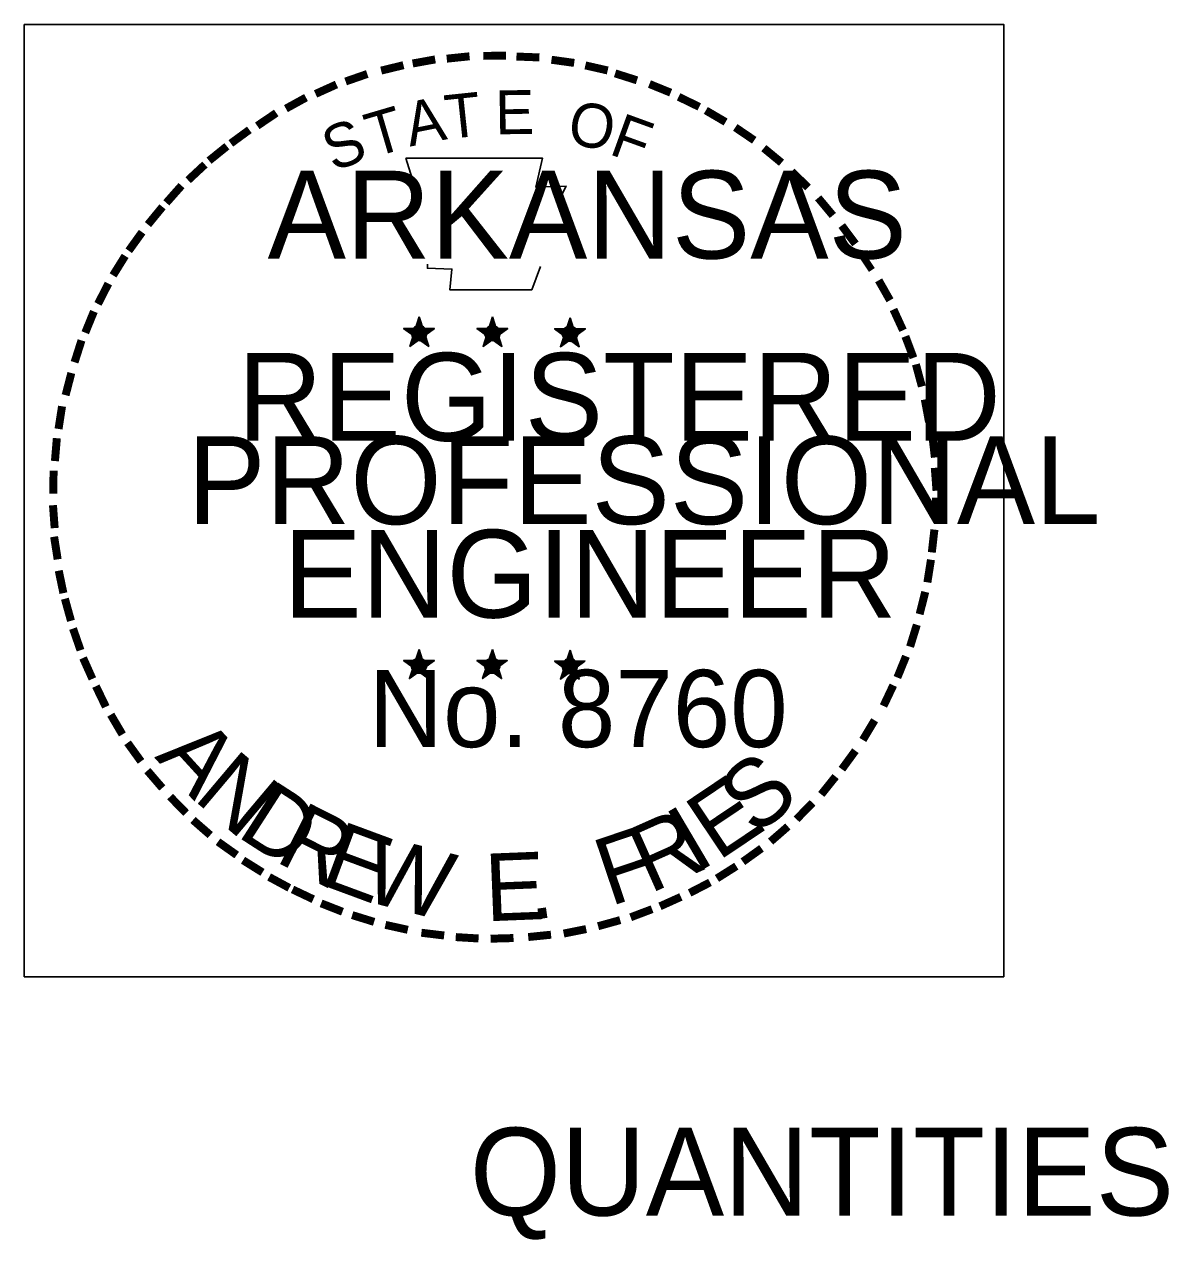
# Model space of a CAD drawing. Extents: x 1226567 to 1228151, y 151309 to 152305.
# Drawn here: x 1227967.3 to 1228130.3, y 151309.4 to 151482.4 of the extents above; entities that cross this region are included whole.
import ezdxf

# ---------------------------------------------------------------- set-up
doc = ezdxf.new("R2010")
doc.units = 0
for name, color, linetype in [('R_Border Notes', 7, 'Continuous'), ('R_Border PE', 7, 'Continuous'), ('R_Border Prem', 7, 'Continuous')]:
    doc.layers.add(name, color=color, linetype=linetype)

msp = doc.modelspace()

# ---------------------------------------------------------------- linework, layer by layer
at = {"layer": 'R_Border PE'}
for p, q in [((1228023.55, 151440.77), (1228023.24, 151439.21)), ((1228023.55, 151440.77), (1228023.3, 151439.15)), ((1228023.55, 151440.77), (1228023.49, 151439.21)), ((1228023.55, 151438.46), (1228023.55, 151440.77)), ((1228023.55, 151440.77), (1228023.99, 151439.15)), ((1228023.55, 151440.77), (1228023.86, 151439.21)), ((1228023.55, 151440.77), (1228023.74, 151439.21)), ((1228033.99, 151440.77), (1228033.68, 151439.21)), ((1228033.99, 151440.77), (1228033.74, 151439.15)), ((1228033.99, 151440.77), (1228033.86, 151439.21)), ((1228033.99, 151438.46), (1228033.99, 151440.77)), ((1228033.99, 151440.77), (1228034.43, 151439.15)), ((1228033.99, 151440.77), (1228034.3, 151439.21)), ((1228033.99, 151440.77), (1228034.11, 151439.21)), ((1228045.05, 151440.65), (1228044.68, 151439.15)), ((1228045.05, 151440.65), (1228044.8, 151439.09)), ((1228045.05, 151440.65), (1228044.93, 151439.09)), ((1228045.05, 151438.4), (1228045.05, 151440.65)), ((1228045.05, 151440.65), (1228045.49, 151439.09)), ((1228045.05, 151440.65), (1228045.36, 151439.09)), ((1228045.05, 151440.65), (1228045.18, 151439.15)), ((1228021.36, 151439.15), (1228023.55, 151438.46)), ((1228021.36, 151439.15), (1228022.99, 151439.02)), ((1228021.36, 151439.15), (1228022.99, 151438.9)), ((1228021.36, 151439.15), (1228022.93, 151438.77)), ((1228021.36, 151439.15), (1228022.93, 151438.52)), ((1228021.36, 151439.15), (1228022.86, 151438.4)), ((1228021.36, 151439.15), (1228022.86, 151438.27)), ((1228022.24, 151436.59), (1228023.55, 151438.46)), ((1228022.24, 151436.59), (1228022.93, 151438.34)), ((1228022.24, 151436.59), (1228022.99, 151438.15)), ((1228022.24, 151436.59), (1228023.11, 151438.09)), ((1228022.24, 151436.59), (1228023.55, 151437.96)), ((1228022.24, 151436.59), (1228023.3, 151437.9)), ((1228022.24, 151436.59), (1228023.61, 151437.77)), ((1228025.74, 151439.15), (1228023.55, 151438.46)), ((1228024.93, 151436.59), (1228023.55, 151438.46)), ((1228024.93, 151436.59), (1228023.55, 151437.96)), ((1228024.93, 151436.59), (1228023.55, 151437.77)), ((1228025.74, 151439.15), (1228023.8, 151439.02)), ((1228024.93, 151436.59), (1228023.8, 151437.9)), ((1228025.74, 151439.15), (1228023.93, 151438.84)), ((1228025.74, 151439.15), (1228023.93, 151438.71)), ((1228024.93, 151436.59), (1228023.99, 151438.15)), ((1228024.93, 151436.59), (1228024.05, 151438.4)), ((1228024.93, 151436.59), (1228024.18, 151438.46)), ((1228025.74, 151439.15), (1228024.36, 151438.59)), ((1228025.74, 151439.15), (1228024.49, 151438.52)), ((1228025.74, 151439.15), (1228024.55, 151438.46)), ((1228031.8, 151439.15), (1228033.99, 151438.46)), ((1228031.8, 151439.15), (1228033.43, 151439.02)), ((1228031.8, 151439.15), (1228033.43, 151438.9)), ((1228031.8, 151439.15), (1228033.36, 151438.77)), ((1228031.8, 151439.15), (1228033.3, 151438.52)), ((1228031.8, 151439.15), (1228033.3, 151438.4)), ((1228031.8, 151439.15), (1228033.3, 151438.27)), ((1228032.68, 151436.59), (1228033.99, 151438.46)), ((1228032.68, 151436.59), (1228033.36, 151438.34)), ((1228032.68, 151436.59), (1228033.43, 151438.15)), ((1228032.68, 151436.59), (1228033.55, 151438.09)), ((1228032.68, 151436.59), (1228033.99, 151437.96)), ((1228032.68, 151436.59), (1228033.74, 151437.9)), ((1228032.68, 151436.59), (1228034.05, 151437.77)), ((1228036.18, 151439.15), (1228033.99, 151438.46)), ((1228035.36, 151436.59), (1228033.99, 151438.46)), ((1228035.36, 151436.59), (1228033.99, 151437.96)), ((1228035.36, 151436.59), (1228033.99, 151437.77)), ((1228036.18, 151439.15), (1228034.24, 151439.02)), ((1228035.36, 151436.59), (1228034.24, 151437.9)), ((1228036.18, 151439.15), (1228034.36, 151438.84)), ((1228036.18, 151439.15), (1228034.36, 151438.71)), ((1228035.36, 151436.59), (1228034.43, 151438.15)), ((1228035.36, 151436.59), (1228034.49, 151438.4)), ((1228035.36, 151436.59), (1228034.61, 151438.46)), ((1228036.18, 151439.15), (1228034.8, 151438.59)), ((1228036.18, 151439.15), (1228034.93, 151438.52)), ((1228036.18, 151439.15), (1228034.99, 151438.46)), ((1228042.86, 151439.09), (1228045.05, 151438.4)), ((1228042.86, 151439.09), (1228044.49, 151438.9)), ((1228042.86, 151439.09), (1228044.43, 151438.77)), ((1228042.86, 151439.09), (1228044.43, 151438.71)), ((1228042.86, 151439.09), (1228044.36, 151438.46)), ((1228042.86, 151439.09), (1228044.36, 151438.34)), ((1228042.86, 151439.09), (1228044.36, 151438.21)), ((1228043.68, 151436.52), (1228045.05, 151438.4)), ((1228043.68, 151436.52), (1228044.43, 151438.27)), ((1228043.68, 151436.52), (1228044.49, 151438.09)), ((1228043.68, 151436.52), (1228044.61, 151438.02)), ((1228043.68, 151436.52), (1228045.05, 151437.9)), ((1228043.68, 151436.52), (1228044.8, 151437.84)), ((1228043.68, 151436.52), (1228045.11, 151437.71)), ((1228047.24, 151439.09), (1228045.05, 151438.4)), ((1228046.36, 151436.52), (1228045.05, 151438.4)), ((1228046.36, 151436.52), (1228045.05, 151437.9)), ((1228046.36, 151436.52), (1228045.05, 151437.71)), ((1228047.24, 151439.09), (1228045.3, 151438.96)), ((1228046.36, 151436.52), (1228045.3, 151437.84)), ((1228047.24, 151439.09), (1228045.43, 151438.77)), ((1228047.24, 151439.09), (1228045.43, 151438.65)), ((1228046.36, 151436.52), (1228045.49, 151438.09)), ((1228046.36, 151436.52), (1228045.55, 151438.34)), ((1228046.36, 151436.52), (1228045.68, 151438.34)), ((1228047.24, 151439.09), (1228045.86, 151438.52)), ((1228047.24, 151439.09), (1228045.93, 151438.46)), ((1228047.24, 151439.09), (1228046.05, 151438.4)), ((1228023.55, 151393.4), (1228023.18, 151391.9)), ((1228023.55, 151393.4), (1228023.3, 151391.84)), ((1228023.55, 151393.4), (1228023.43, 151391.84)), ((1228023.55, 151391.15), (1228023.55, 151393.4)), ((1228023.55, 151393.4), (1228023.99, 151391.84)), ((1228023.55, 151393.4), (1228023.86, 151391.84)), ((1228023.55, 151393.4), (1228023.68, 151391.84)), ((1228033.99, 151393.4), (1228033.61, 151391.9)), ((1228033.99, 151393.4), (1228033.74, 151391.84)), ((1228033.99, 151393.4), (1228033.86, 151391.84)), ((1228033.99, 151391.15), (1228033.99, 151393.4)), ((1228033.99, 151393.4), (1228034.36, 151391.84)), ((1228033.99, 151393.4), (1228034.3, 151391.84)), ((1228033.99, 151393.4), (1228034.11, 151391.84)), ((1228045.05, 151393.34), (1228044.68, 151391.77)), ((1228045.05, 151393.34), (1228044.8, 151391.77)), ((1228045.05, 151393.34), (1228044.93, 151391.77)), ((1228045.05, 151391.09), (1228045.05, 151393.34)), ((1228045.05, 151393.34), (1228045.43, 151391.77)), ((1228045.05, 151393.34), (1228045.36, 151391.77)), ((1228045.05, 151393.34), (1228045.18, 151391.77)), ((1228021.36, 151391.84), (1228023.55, 151391.15)), ((1228021.36, 151391.84), (1228022.99, 151391.65)), ((1228021.36, 151391.84), (1228022.93, 151391.52)), ((1228021.36, 151391.84), (1228022.93, 151391.46)), ((1228021.36, 151391.84), (1228022.86, 151391.21)), ((1228021.36, 151391.84), (1228022.86, 151391.09)), ((1228021.36, 151391.84), (1228022.86, 151390.96)), ((1228022.18, 151389.27), (1228023.55, 151391.15)), ((1228022.18, 151389.27), (1228022.93, 151391.02)), ((1228025.74, 151391.84), (1228023.55, 151391.15)), ((1228024.86, 151389.27), (1228023.55, 151391.15)), ((1228025.74, 151391.84), (1228023.8, 151391.71)), ((1228025.74, 151391.84), (1228023.93, 151391.52)), ((1228025.74, 151391.84), (1228023.93, 151391.4)), ((1228024.86, 151389.27), (1228023.99, 151391.09)), ((1228024.86, 151389.27), (1228024.18, 151391.09)), ((1228025.74, 151391.84), (1228024.3, 151391.27)), ((1228025.74, 151391.84), (1228024.43, 151391.21)), ((1228025.74, 151391.84), (1228024.55, 151391.09)), ((1228031.8, 151391.84), (1228033.99, 151391.15)), ((1228031.8, 151391.84), (1228033.36, 151391.65)), ((1228031.8, 151391.84), (1228033.36, 151391.52)), ((1228031.8, 151391.84), (1228033.36, 151391.46)), ((1228031.8, 151391.84), (1228033.3, 151391.21)), ((1228031.8, 151391.84), (1228033.3, 151391.09)), ((1228031.8, 151391.84), (1228033.3, 151390.96)), ((1228032.61, 151389.27), (1228033.99, 151391.15)), ((1228032.61, 151389.27), (1228033.36, 151391.02)), ((1228036.11, 151391.84), (1228033.99, 151391.15)), ((1228035.3, 151389.27), (1228033.99, 151391.15)), ((1228036.11, 151391.84), (1228034.24, 151391.71)), ((1228036.11, 151391.84), (1228034.36, 151391.52)), ((1228036.11, 151391.84), (1228034.36, 151391.4)), ((1228035.3, 151389.27), (1228034.43, 151391.09)), ((1228035.3, 151389.27), (1228034.61, 151391.09)), ((1228036.11, 151391.84), (1228034.74, 151391.27)), ((1228036.11, 151391.84), (1228034.86, 151391.21)), ((1228036.11, 151391.84), (1228034.99, 151391.09)), ((1228042.86, 151391.77), (1228045.05, 151391.09)), ((1228042.86, 151391.77), (1228044.43, 151391.59)), ((1228042.86, 151391.77), (1228044.43, 151391.46)), ((1228042.86, 151391.77), (1228044.36, 151391.34)), ((1228042.86, 151391.77), (1228044.36, 151391.15)), ((1228042.86, 151391.77), (1228044.3, 151390.96)), ((1228042.86, 151391.77), (1228044.3, 151390.84)), ((1228043.68, 151389.21), (1228045.05, 151391.09)), ((1228043.68, 151389.21), (1228044.36, 151390.96)), ((1228047.18, 151391.77), (1228045.05, 151391.09)), ((1228046.36, 151389.21), (1228045.05, 151391.09)), ((1228047.18, 151391.77), (1228045.3, 151391.65)), ((1228047.18, 151391.77), (1228045.43, 151391.46)), ((1228047.18, 151391.77), (1228045.43, 151391.34)), ((1228046.36, 151389.21), (1228045.49, 151391.02)), ((1228046.36, 151389.21), (1228045.61, 151391.02)), ((1228047.18, 151391.77), (1228045.8, 151391.21)), ((1228047.18, 151391.77), (1228045.93, 151391.09)), ((1228047.18, 151391.77), (1228045.99, 151391.02)), ((1228022.18, 151389.27), (1228022.99, 151390.77)), ((1228022.18, 151389.27), (1228023.11, 151390.71)), ((1228022.18, 151389.27), (1228023.55, 151390.65)), ((1228022.18, 151389.27), (1228023.3, 151390.59)), ((1228022.18, 151389.27), (1228023.55, 151390.46)), ((1228024.86, 151389.27), (1228023.49, 151390.46)), ((1228024.86, 151389.27), (1228023.55, 151390.59)), ((1228024.86, 151389.27), (1228023.74, 151390.59)), ((1228024.86, 151389.27), (1228023.99, 151390.84)), ((1228032.61, 151389.27), (1228033.43, 151390.77)), ((1228032.61, 151389.27), (1228033.55, 151390.71)), ((1228032.61, 151389.27), (1228033.99, 151390.65)), ((1228032.61, 151389.27), (1228033.74, 151390.59)), ((1228032.61, 151389.27), (1228033.99, 151390.46)), ((1228035.3, 151389.27), (1228033.93, 151390.46)), ((1228035.3, 151389.27), (1228033.99, 151390.59)), ((1228035.3, 151389.27), (1228034.18, 151390.59)), ((1228035.3, 151389.27), (1228034.43, 151390.84)), ((1228043.68, 151389.21), (1228044.43, 151390.71)), ((1228043.68, 151389.21), (1228044.61, 151390.65)), ((1228043.68, 151389.21), (1228044.8, 151390.52)), ((1228043.68, 151389.21), (1228044.99, 151390.52)), ((1228043.68, 151389.21), (1228045.05, 151390.4)), ((1228046.36, 151389.21), (1228044.99, 151390.52)), ((1228046.36, 151389.21), (1228044.99, 151390.34)), ((1228046.36, 151389.21), (1228045.24, 151390.52)), ((1228046.36, 151389.21), (1228045.43, 151390.71))]:
    msp.add_line(p, q, dxfattribs=at)
for points in [[(1228021.68, 151463.4), (1228023.3, 151458.21)], [(1228043.61, 151457.65), (1228044.49, 151459.4), (1228040.18, 151459.27), (1228041.11, 151463.4), (1228021.68, 151463.4)], [(1228024.74, 151448.27), (1228024.74, 151447.71), (1228028.24, 151447.59), (1228027.93, 151444.65), (1228039.61, 151444.65), (1228040.86, 151447.96)], [(1228023.55, 151440.77), (1228024.93, 151436.59), (1228021.36, 151439.15), (1228025.74, 151439.15), (1228022.24, 151436.59), (1228023.55, 151440.77)], [(1228033.99, 151440.77), (1228035.36, 151436.59), (1228031.8, 151439.15), (1228036.18, 151439.15), (1228032.68, 151436.59), (1228033.99, 151440.77)], [(1228045.05, 151440.65), (1228046.36, 151436.52), (1228042.86, 151439.09), (1228047.24, 151439.09), (1228043.68, 151436.52), (1228045.05, 151440.65)], [(1228023.55, 151393.4), (1228024.86, 151389.27), (1228021.36, 151391.84), (1228025.74, 151391.84), (1228022.18, 151389.27), (1228023.55, 151393.4)], [(1228033.99, 151393.4), (1228035.3, 151389.27), (1228031.8, 151391.84), (1228036.11, 151391.84), (1228032.61, 151389.27), (1228033.99, 151393.4)], [(1228045.05, 151393.34), (1228046.36, 151389.21), (1228042.86, 151391.77), (1228047.18, 151391.77), (1228043.68, 151389.21), (1228045.05, 151393.34)]]:
    msp.add_lwpolyline(points, dxfattribs=at)
for centre, radius in [((1228023.57, 151438.46), 1.08), ((1228023.57, 151438.46), 0.975), ((1228023.57, 151438.46), 0.904), ((1228034, 151438.46), 1.08), ((1228034, 151438.46), 0.975), ((1228034, 151438.46), 0.904), ((1228045.05, 151438.38), 1.08), ((1228045.05, 151438.38), 0.975), ((1228023.57, 151438.46), 0.83), ((1228023.57, 151438.46), 0.723), ((1228023.57, 151438.46), 0.672), ((1228023.57, 151438.46), 0.619), ((1228023.57, 151438.46), 0.533), ((1228023.57, 151438.46), 0.467), ((1228023.57, 151438.46), 0.388), ((1228023.57, 151438.46), 0.31), ((1228023.57, 151438.46), 0.231), ((1228023.57, 151438.46), 0.185), ((1228023.57, 151438.46), 0.0901), ((1228034, 151438.46), 0.83), ((1228034, 151438.46), 0.723), ((1228034, 151438.46), 0.672), ((1228034, 151438.46), 0.619), ((1228034, 151438.46), 0.533), ((1228034, 151438.46), 0.467), ((1228034, 151438.46), 0.388), ((1228034, 151438.46), 0.31), ((1228034, 151438.46), 0.231), ((1228034, 151438.46), 0.185), ((1228034, 151438.46), 0.0901), ((1228045.05, 151438.38), 0.904), ((1228045.05, 151438.38), 0.83), ((1228045.05, 151438.38), 0.723), ((1228045.05, 151438.38), 0.672), ((1228045.05, 151438.38), 0.619), ((1228045.05, 151438.38), 0.533), ((1228045.05, 151438.38), 0.467), ((1228045.05, 151438.38), 0.388), ((1228045.05, 151438.38), 0.31), ((1228045.05, 151438.38), 0.231), ((1228045.05, 151438.38), 0.185), ((1228045.05, 151438.38), 0.0901), ((1228023.54, 151391.12), 1.08), ((1228023.54, 151391.12), 0.975), ((1228023.54, 151391.12), 0.904), ((1228023.54, 151391.12), 0.83), ((1228023.54, 151391.12), 0.723), ((1228023.54, 151391.12), 0.672), ((1228023.54, 151391.12), 0.619), ((1228023.54, 151391.12), 0.533), ((1228023.54, 151391.12), 0.467), ((1228023.54, 151391.12), 0.388), ((1228023.54, 151391.12), 0.31), ((1228023.54, 151391.12), 0.231), ((1228023.54, 151391.12), 0.185), ((1228023.54, 151391.12), 0.0901), ((1228033.98, 151391.12), 1.08), ((1228033.98, 151391.12), 0.975), ((1228033.98, 151391.12), 0.904), ((1228033.98, 151391.12), 0.83), ((1228033.98, 151391.12), 0.723), ((1228033.98, 151391.12), 0.672), ((1228033.98, 151391.12), 0.619), ((1228033.98, 151391.12), 0.533), ((1228033.98, 151391.12), 0.467), ((1228033.98, 151391.12), 0.388), ((1228033.98, 151391.12), 0.31), ((1228033.98, 151391.12), 0.231), ((1228033.98, 151391.12), 0.185), ((1228033.98, 151391.12), 0.0901), ((1228045.02, 151391.05), 1.08), ((1228045.02, 151391.05), 0.975), ((1228045.02, 151391.05), 0.904), ((1228045.02, 151391.05), 0.83), ((1228045.02, 151391.05), 0.723), ((1228045.02, 151391.05), 0.672), ((1228045.02, 151391.05), 0.619), ((1228045.02, 151391.05), 0.533), ((1228045.02, 151391.05), 0.467), ((1228045.02, 151391.05), 0.388), ((1228045.02, 151391.05), 0.31), ((1228045.02, 151391.05), 0.231), ((1228045.02, 151391.05), 0.185), ((1228045.02, 151391.05), 0.0901)]:
    msp.add_circle(centre, radius, dxfattribs=at)
at = {"layer": 'R_Border Prem'}
msp.add_lwpolyline([(1227967.33, 151482.44), (1228106.83, 151482.44), (1228106.83, 151346.82), (1227967.33, 151346.82)], close=True, dxfattribs=at)

# ---------------------------------------------------------------- texts
at = {"layer": 'R_Border Notes'}
msp.add_text('QUANTITIES', height=12.5, dxfattribs=at).set_placement((1228030.78, 151312.82))
at = {"layer": 'R_Border PE'}
for s, height, rotation, p in [('-', 10, 10.2193, (1228022.74, 151472.96)), ('-', 10, 5.8968, (1228027.3, 151473.65)), ('-', 10, 0.1862, (1228032.11, 151474.09)), ('-', 10, 357.743, (1228036.68, 151474.02)), ('-', 10, 352.1617, (1228041.3, 151473.65)), ('-', 10, 19.1761, (1228013.8, 151470.46)), ('-', 10, 13.6302, (1228018.49, 151471.96)), ('-', 10, 347.2049, (1228045.8, 151472.96)), ('-', 10, 342.3362, (1228049.74, 151471.96)), ('-', 10, 24.3072, (1228009.86, 151468.77)), ('-', 10, 337.8551, (1228054.36, 151470.59)), ('-', 10, 28.7918, (1228005.93, 151466.77)), ('T', 6.25, 6.0228, (1228027.55, 151466.09)), ('E', 6.25, 0.8323, (1228034.43, 151466.77)), ('-', 10, 334.1211, (1228058.3, 151468.9)), ('T', 6.25, 16.4036, (1228017.05, 151463.46)), ('A', 6.25, 11.2132, (1228022.24, 151465.02)), ('O', 6.25, 350.4515, (1228044.49, 151465.46)), ('-', 10, 329.6409, (1228061.93, 151467.15)), ('-', 10, 34.0636, (1228002.18, 151464.46)), ('F', 6.25, 340.0707, (1228050.43, 151464.02)), ('-', 10, 36.2317, (1227998.55, 151462.02)), ('S', 6.25, 21.594, (1228011.36, 151461.4)), ('-', 10, 325.8627, (1228065.93, 151464.9)), ('-', 10, 38.9507, (1227995.61, 151459.65)), ('-', 10, 320.5297, (1228069.74, 151462.21)), ('-', 10, 42.9622, (1227992.86, 151457.02)), ('-', 10, 315.5786, (1228073.49, 151459.15)), ('-', 10, 48.423, (1227990.05, 151454.02)), ('-', 10, 50.6142, (1227987.55, 151451.02)), ('-', 10, 309.8797, (1228077.05, 151455.71)), ('-', 10, 54.2325, (1227984.99, 151447.46)), ('-', 10, 306.6522, (1228080.3, 151451.96)), ('-', 10, 58.0706, (1227982.93, 151444.15)), ('-', 8.75, 303.6753, (1228083.36, 151448.4)), ('-', 10, 299.6684, (1228085.36, 151444.59)), ('-', 10, 62.8713, (1227980.99, 151440.34)), ('-', 10, 67.7743, (1227979.36, 151436.52)), ('-', 10, 294.6628, (1228087.36, 151440.77)), ('-', 10, 72.3945, (1227977.99, 151432.59)), ('-', 10, 290.5728, (1228088.99, 151437.21)), ('-', 10, 285.1233, (1228090.43, 151433.59)), ('-', 10, 75.461, (1227976.8, 151428.09)), ('-', 10, 280.5493, (1228091.68, 151428.9)), ('-', 10, 81.2013, (1227975.93, 151423.65)), ('-', 10, 276.5962, (1228092.74, 151424.15)), ('-', 10, 85.1863, (1227975.49, 151419.34)), ('-', 10, 89.0622, (1227975.3, 151414.96)), ('-', 10, 274.3301, (1228093.11, 151419.59)), ('-', 10, 94.1959, (1227975.55, 151410.4)), ('-', 10, 269.9407, (1228093.3, 151415.65)), ('-', 10, 263.5172, (1228093.18, 151411.52)), ('-', 10, 98.9479, (1227975.99, 151406.27)), ('-', 10, 101.7149, (1227976.8, 151401.65)), ('-', 10, 260.9953, (1228092.74, 151407.4)), ('-', 10, 255.7626, (1228092.05, 151403.15)), ('-', 10, 105.4578, (1227977.86, 151397.96)), ('-', 10, 109.0874, (1227979.18, 151394.02)), ('-', 10, 252.8681, (1228090.93, 151398.65)), ('-', 10, 247.8887, (1228089.55, 151394.46)), ('-', 10, 114.0643, (1227980.8, 151390.27)), ('-', 10, 115.7289, (1227982.68, 151386.4)), ('-', 10, 244.6197, (1228087.86, 151390.52)), ('-', 10, 120.4471, (1227984.93, 151382.77)), ('-', 10, 239.0712, (1228085.43, 151385.84)), ('A', 9.62, 312.4727, (1227985.8, 151378.08)), ('-', 10, 125.8934, (1227987.43, 151379.27)), ('N', 9.62, 319.8362, (1227991.23, 151372.15)), ('-', 10, 233.8452, (1228082.93, 151381.77)), ('S', 9.62, 39.723, (1228071.47, 151366.68)), ('-', 10, 130.7181, (1227990.3, 151375.77)), ('E', 9.62, 33.8878, (1228066.13, 151363.2)), ('-', 10, 231.2538, (1228080.24, 151378.21)), ('D', 9.62, 327.1996, (1227997.38, 151366.96)), ('-', 10, 134.2238, (1227993.55, 151372.4)), ('-', 10, 225.7653, (1228077.24, 151374.71)), ('R', 9.62, 333.1738, (1228002.82, 151363.36)), ('R', 9.62, 24.0235, (1228056.39, 151358.6)), ('I', 9.62, 30.5534, (1228062.93, 151361.46)), ('-', 10, 138.9338, (1227996.8, 151369.52)), ('E', 9.62, 339.7037, (1228009.17, 151360.09)), ('-', 10, 221.0851, (1228073.99, 151371.52)), ('W', 9.62, 345.5389, (1228015.12, 151357.8)), ('F', 9.62, 18.6051, (1228050.75, 151356.81)), ('-', 10, 144.6463, (1228000.3, 151366.96)), ('-', 10, 215.7363, (1228070.55, 151368.59)), ('-', 10, 148.0898, (1228003.8, 151364.65)), ('E', 9.62, 2.2804, (1228033.09, 151354.71)), ('-', 10, 151.5704, (1228007.43, 151362.59)), ('-', 10, 212.2491, (1228067.18, 151366.15)), ('-', 10, 154.6002, (1228010.68, 151361.09)), ('-', 10, 207.3568, (1228063.74, 151363.96)), ('-', 10, 204.2516, (1228059.8, 151361.96)), ('-', 10, 158.5612, (1228014.61, 151359.46)), ('.', 9.62, 8.1156, (1228039.46, 151354.88)), ('-', 10, 200.7184, (1228055.93, 151360.27)), ('-', 10, 162.7983, (1228018.86, 151358.15)), ('-', 10, 167.5555, (1228023.36, 151357.15)), ('-', 10, 195.4743, (1228051.74, 151358.77)), ('-', 10, 173.1155, (1228028.18, 151356.46)), ('-', 10, 176.5183, (1228032.86, 151356.09)), ('-', 10, 181.5918, (1228037.49, 151356.21)), ('-', 10, 185.8167, (1228042.55, 151356.71)), ('-', 10, 191.2858, (1228047.18, 151357.52))]:
    msp.add_text(s, height=height, rotation=rotation, dxfattribs=at).set_placement(p)
for s, height, p in [('ARKANSAS', 12.5, (1228001.99, 151449.09)), ('REGISTERED', 12.5, (1227997.74, 151423.15)), ('PROFESSIONAL', 12.4999, (1227990.55, 151411.27)), ('ENGINEER', 12.5, (1228004.24, 151397.96)), ('No. 8760', 11, (1228016.35, 151379.52))]:
    msp.add_text(s, height=height, dxfattribs=at).set_placement(p)

doc.saveas('drawing.dxf')
